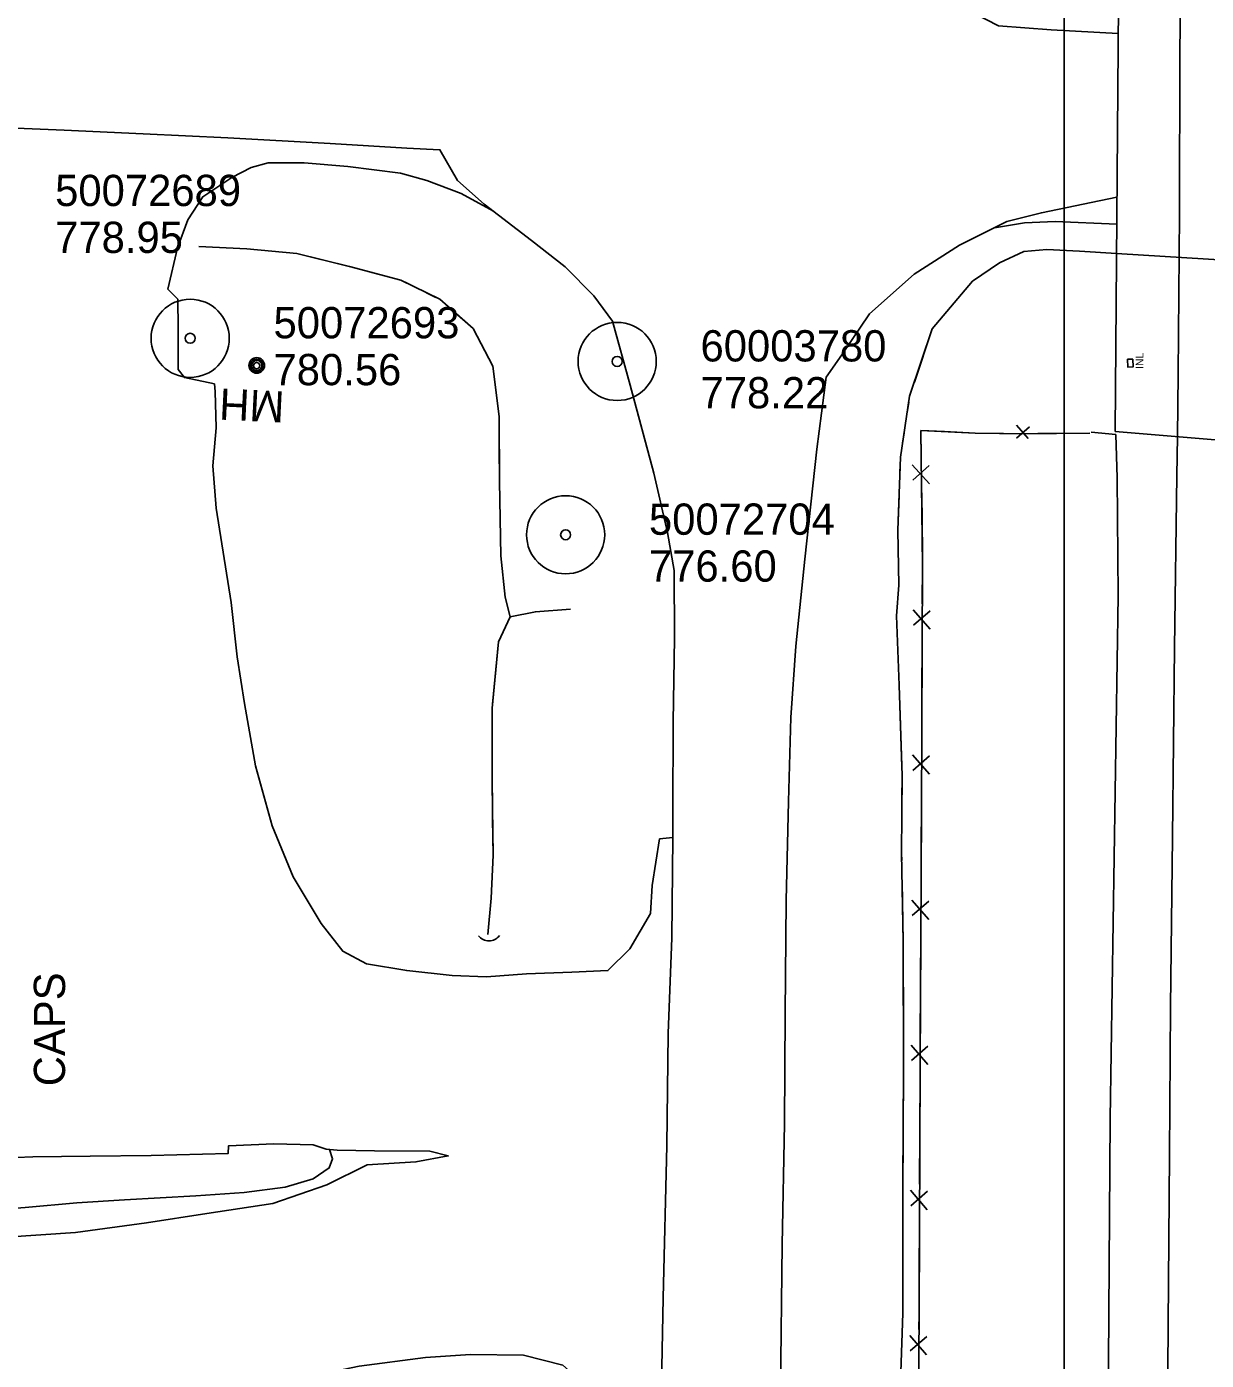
# Model space of a CAD drawing. Extents: x 591954 to 597000, y 198576 to 213500.
# Drawn here: x 593800.8 to 594027.3, y 204597.1 to 204853.1 of the extents above; entities that cross this region are included whole.
import ezdxf

# ---------------------------------------------------------------- set-up
doc = ezdxf.new("R2010")
doc.units = 0
for name, color, linetype in [('Level 10', 7, 'Continuous'), ('Level 11', 7, 'Continuous'), ('Level 15', 7, 'Continuous'), ('Level 16', 7, 'Continuous'), ('Level 17', 7, 'Continuous'), ('Level 19', 7, 'Continuous'), ('Level 6', 7, 'Continuous')]:
    doc.layers.add(name, color=color, linetype=linetype)

msp = doc.modelspace()

# ---------------------------------------------------------------- linework, layer by layer
at = {"layer": 'Level 10'}
for p, q in [((594000, 204500), (594000, 206500)), ((594000, 204500), (594000, 206500)), ((594000, 204500), (594000, 206000)), ((594000, 204000), (594000, 205500)), ((594000, 203500), (594000, 205000))]:
    msp.add_line(p, q, dxfattribs=at)
at = {"layer": 'Level 11'}
for points in [[(593950.48, 204940.73), (593951.05, 204934.39), (593952.29, 204922.71), (593954.97, 204909.56), (593958.15, 204894.43), (593961.95, 204883.36), (593965.83, 204875.09), (593970.65, 204867.79), (593974.61, 204862.06), (593980.17, 204856.96), (593987.4, 204853.29), (593997.5, 204852.51), (594010.4, 204851.83)], [(594022.76, 204897.49), (594022.54, 204875.93), (594022.24, 204847.98), (594022.19, 204817.13), (594021.94, 204786.42), (594021.78, 204774.42)], [(593791.02, 204833.98), (593808.02, 204833.27), (593823.21, 204832.55), (593839.44, 204831.79), (593859.12, 204830.68), (593873.81, 204829.8), (593880.16, 204829.49), (593883.57, 204823.57), (593888.64, 204819.05), (593897.72, 204812.1), (593904.21, 204807.02), (593909.73, 204801.46), (593913.31, 204796.6), (593916.69, 204784.31), (593921.23, 204767.39), (593923.86, 204756.03), (593925.16, 204748.73), (593925.23, 204735.76), (593924.93, 204719.68), (593924.89, 204702.24), (593924.86, 204697.49)], [(593890.44, 204817.68), (593884.23, 204821.08), (593877.62, 204823.56), (593872.62, 204824.98), (593862.5, 204826.29), (593854.12, 204826.99), (593847.18, 204827.01)], [(594010.16, 204820.36), (593995.67, 204817.39), (593989.04, 204815.71), (593979.91, 204811.2), (593971.2, 204805.58), (593962.63, 204797.96), (593957.32, 204790.14), (593954.3, 204785.86), (593952.52, 204771.98), (593950.25, 204750.88), (593948.49, 204734.2), (593947.55, 204720.51), (593947.08, 204704.38), (593946.66, 204685.38), (593946.43, 204663.69), (593946.32, 204642.47), (593945.89, 204619.32), (593945.56, 204591.42)], [(594010.11, 204815.21), (593998.32, 204815.74), (593992.41, 204815.46), (593986.64, 204814.52)], [(594021.78, 204774.42), (594021.68, 204766.91), (594021.23, 204733.87), (594020.85, 204697.5), (594020.43, 204664.97), (594020.23, 204636.55), (594020.02, 204603.94), (594019.79, 204577.76), (594019.36, 204543.85), (594018.8, 204510.12), (594018.68, 204480.65), (594018.25, 204441.53), (594018.05, 204410.9), (594017.91, 204399.22), (594017.15, 204332.99), (594016.82, 204297.15), (594016.34, 204268.02), (594016.06, 204236.2), (594015.78, 204207.45), (594015.48, 204178.53), (594015.23, 204165.45)], [(593924.86, 204697.49), (593924.7, 204678.23)], [(593924.7, 204678.23), (593923.99, 204659.86), (593923.72, 204638.26), (593923.06, 204609.1), (593922.53, 204582.42), (593922.49, 204571.57)]]:
    msp.add_lwpolyline(points, dxfattribs=at)
at = {"layer": 'Level 15'}
for p, q in [((593993.09, 204774.09), (593990.86, 204776.64)), ((593993.38, 204776.32), (593990.87, 204774.15)), ((593970.87, 204769.01), (593974.15, 204765.33)), ((593974.11, 204768.88), (593970.97, 204766.04)), ((593971.05, 204741.18), (593974.27, 204737.45)), ((593974.29, 204740.99), (593971.1, 204738.21)), ((593970.93, 204713.32), (593974.15, 204709.59)), ((593974.17, 204713.14), (593970.99, 204710.35)), ((593970.79, 204685.46), (593974.01, 204681.73)), ((593974.03, 204685.27), (593970.84, 204682.49)), ((593970.64, 204657.6), (593973.86, 204653.87)), ((593973.88, 204657.41), (593970.69, 204654.64)), ((593970.53, 204629.74), (593973.75, 204626.01)), ((593973.76, 204629.56), (593970.58, 204626.77)), ((593970.4, 204601.89), (593973.61, 204598.14)), ((593973.64, 204601.69), (593970.45, 204598.92))]:
    msp.add_line(p, q, dxfattribs=at)
for points in [[(594009.8, 204775.43), (594035.18, 204773.29), (594055.09, 204771.47), (594079.19, 204769.38), (594103.38, 204767.91), (594131.62, 204766.14), (594132.69, 204886.85), (594113.93, 204889.15), (594088.57, 204892.2), (594057.68, 204894.45), (594010.77, 204898.53), (594009.8, 204775.43)], [(594013.21, 204789.31), (594012.21, 204789.28), (594012.25, 204787.78), (594013.25, 204787.81), (594013.21, 204789.31)], [(594004.93, 204775.07), (593992.24, 204774.97), (593982.91, 204775.11), (593972.53, 204775.59), (593972.83, 204749.67), (593972.62, 204702.6), (593972.36, 204653.67), (593972.17, 204605.99), (593971.69, 204540.87), (593971.38, 204493.61), (593971.2, 204445.1), (593971, 204397.45), (593970.28, 204351.21), (593970.53, 204303.06), (593970.73, 204279)], [(593977.08, 204775.38), (593972.53, 204775.59), (593972.59, 204770.19)], [(593988.4, 204775.03), (593982.91, 204775.11), (593977.08, 204775.38)], [(594004.93, 204775.07), (593994.98, 204774.99)], [(594009.92, 204774.8), (594005.24, 204775.27)], [(594009.92, 204774.8), (594010.23, 204766.5), (594010.39, 204743.84), (594008.84, 204643.53), (594008.37, 204568.66), (594006.82, 204443.45), (594006.02, 204341.34)], [(593972.67, 204763.61), (593972.8, 204752.29)], [(593972.8, 204752.29), (593972.83, 204749.67), (593972.79, 204742.33)], [(593972.77, 204735.75), (593972.72, 204724.43)], [(593972.72, 204724.43), (593972.68, 204714.47)], [(593972.65, 204707.89), (593972.62, 204702.6), (593972.59, 204696.57)], [(593972.59, 204696.57), (593972.54, 204686.61)], [(593972.5, 204680.03), (593972.44, 204668.71)], [(593972.44, 204668.71), (593972.38, 204658.75)], [(593972.35, 204652.17), (593972.31, 204640.85)], [(593972.31, 204640.85), (593972.27, 204630.89)], [(593972.24, 204624.31), (593972.2, 204612.99)], [(593972.2, 204612.99), (593972.17, 204605.99), (593972.15, 204603.03)]]:
    msp.add_lwpolyline(points, dxfattribs=at)
msp.add_arc((593889.57, 204680.11), 2.5, 217.2794, 323.519, dxfattribs=at)
at = {"layer": 'Level 16'}
for centre, radius in [((593844.99, 204788.08), 1.5), ((593844.99, 204788.07), 1.22), ((593844.99, 204788.06), 0.968), ((593844.96, 204788.05), 0.605)]:
    msp.add_circle(centre, radius, dxfattribs=at)
at = {"layer": 'Level 17'}
for points in [[(593924.86, 204697.49), (593922.34, 204697.19), (593920.94, 204688.26), (593920.58, 204682.85), (593916.66, 204676.11), (593912.42, 204671.9), (593905.51, 204671.6), (593896.76, 204671.31), (593889.09, 204670.74), (593882.53, 204670.94), (593873.8, 204671.91), (593866.08, 204673.2), (593861.51, 204675.64), (593857.38, 204680.96), (593852.01, 204689.92), (593847.95, 204699.7), (593844.73, 204711.19), (593842.65, 204723.16), (593841.26, 204732.12), (593840.05, 204742.59), (593837.19, 204760.7), (593836.59, 204768.79), (593837.22, 204776.08), (593837.02, 204783.11), (593836.87, 204784.54), (593831.09, 204785.76), (593829.92, 204787.32), (593829.89, 204795.26), (593829.82, 204800.82), (593827.93, 204802.74), (593829.77, 204810.69), (593831.74, 204816.02), (593834.63, 204820.48), (593840.18, 204824.15), (593843.91, 204826.08), (593847.18, 204827.01)], [(593789.38, 204635.67), (593802.01, 204636.14), (593813.01, 204636.29), (593824.75, 204636.43), (593839.51, 204636.81), (593839.55, 204638.27), (593848.26, 204638.67), (593855.84, 204638.49), (593858.31, 204637.64), (593860.42, 204637.46), (593867.58, 204637.31), (593878.23, 204637.23), (593881.77, 204636.34), (593875.55, 204635.19), (593866.21, 204634.6), (593858.48, 204630.8), (593848.06, 204627.17), (593835.38, 204625.27), (593823.81, 204623.47), (593810.19, 204621.61), (593796.85, 204620.72)], [(593858.93, 204637.59), (593859.56, 204635.79), (593858.92, 204634.04), (593855.85, 204631.94), (593850.45, 204630.32), (593842.58, 204629.32), (593833.28, 204628.66), (593819.62, 204627.89), (593810.45, 204627.35), (593800.52, 204626.45), (593788.92, 204625.51), (593777.95, 204624.55), (593765.33, 204623.12), (593752.81, 204622.01), (593741.79, 204620.1), (593730.93, 204618.11), (593719.49, 204615.39), (593710.09, 204612.46), (593705.52, 204609.13), (593696.51, 204607.23), (593683.76, 204605.92), (593677.44, 204607.17)], [(593790.71, 204441.53), (593794.48, 204450.19), (593797.09, 204460.81), (593797.94, 204478.07), (593798.46, 204497.19), (593798.75, 204519.3), (593799.26, 204537.02), (593799.81, 204564.18), (593801.19, 204573.06), (593808.05, 204580.23), (593829.75, 204587.56), (593852.05, 204593.34), (593864.66, 204596), (593877.42, 204597.64), (593886.03, 204598.2), (593896.24, 204598.08), (593903.76, 204596.18), (593910.27, 204590.43), (593916.37, 204584.74), (593919.67, 204577.68), (593922.49, 204571.57)]]:
    msp.add_lwpolyline(points, dxfattribs=at)
at = {"layer": 'Level 19'}
for points in [[(593833.86, 204810.94), (593843.08, 204810.5), (593852.67, 204809.6), (593862.83, 204807.07), (593872.68, 204804.45), (593880.13, 204800.78), (593886.52, 204795.15), (593890.35, 204787.96), (593891.54, 204778.26), (593891.58, 204765.81), (593891.85, 204751.56), (593892.68, 204743.59), (593893.65, 204739.84)], [(593833.86, 204810.94), (593843.08, 204810.5), (593852.67, 204809.6), (593862.5, 204807.15)], [(593987.59, 204807.77), (593992.27, 204809.94), (593996.71, 204810.33), (594002.98, 204810.01), (594010.07, 204809.57)], [(594010.07, 204809.57), (594002.98, 204810.01), (593996.71, 204810.33), (593992.27, 204809.94), (593987.59, 204807.77)], [(594010.07, 204809.57), (594131.76, 204802.06)], [(593987.59, 204807.77), (593982.45, 204804.28), (593974.67, 204795.11), (593970.36, 204782.19), (593968.59, 204770.46), (593968.08, 204756.48), (593968.3, 204745.92), (593967.82, 204740)], [(593987.59, 204807.77), (593982.45, 204804.28), (593974.67, 204795.11), (593971.26, 204784.9)], [(593866.37, 204806.12), (593868.3, 204805.61)], [(593872.17, 204804.58), (593872.68, 204804.45), (593874, 204803.8)], [(593877.59, 204802.03), (593879.38, 204801.15)], [(593882.51, 204798.68), (593886.52, 204795.15), (593890.35, 204787.96), (593891.54, 204778.26), (593891.56, 204772.53)], [(593970.19, 204781.06), (593969.89, 204779.08)], [(593969.29, 204775.13), (593969, 204773.15)], [(593891.56, 204772.53), (593891.58, 204765.81), (593891.85, 204751.56), (593892.68, 204743.59), (593892.69, 204743.57)], [(593968.54, 204769.18), (593968.47, 204767.18)], [(593968.33, 204763.19), (593968.08, 204756.48), (593968.3, 204745.92), (593967.82, 204740)], [(593905.21, 204741.27), (593898.49, 204740.81), (593893.65, 204739.84), (593891.44, 204735), (593890.21, 204722.31), (593890.19, 204707.76), (593890.38, 204694.08), (593889.99, 204685.82), (593889.39, 204678.86)], [(593890.28, 204723.05), (593891.44, 204735), (593893.65, 204739.84), (593898.49, 204740.81), (593905.21, 204741.27)], [(593967.82, 204740), (593968.36, 204726.69), (593968.9, 204709.31), (593968.81, 204694.43), (593969.09, 204677.52), (593969.2, 204652.82), (593969.06, 204629.08), (593969.05, 204606.13), (593968.52, 204590.97)], [(593967.82, 204740), (593968.36, 204726.69), (593968.84, 204711.02)], [(593890.2, 204717.05), (593890.2, 204719.05)], [(593890.2, 204711.05), (593890.2, 204713.05)], [(593890.23, 204705.05), (593890.2, 204707.05)], [(593968.88, 204707.02), (593968.87, 204705.02)], [(593889.39, 204678.86), (593889.99, 204685.82), (593890.38, 204694.08), (593890.29, 204701.05)], [(593968.85, 204701.02), (593968.84, 204699.02)], [(593968.81, 204695.02), (593968.81, 204694.43), (593968.83, 204693.02)], [(593968.9, 204689.02), (593969.09, 204677.52), (593969.17, 204660.02)], [(593969.17, 204660.02), (593969.2, 204652.82), (593969.07, 204631.02)], [(593969.06, 204627.02), (593969.06, 204625.02)], [(593969.06, 204621.02), (593969.06, 204619.02)], [(593969.06, 204615.02), (593969.06, 204613.02)], [(593969.06, 204609.02), (593969.05, 204606.13), (593968.52, 204590.97), (593968.53, 204580.03)]]:
    msp.add_lwpolyline(points, dxfattribs=at)
at = {"layer": 'Level 6'}
for centre, radius in [((593832.21, 204793.29), 7.5), ((593832.21, 204793.29), 7.5), ((593832.21, 204793.29), 7.5), ((593832.21, 204793.29), 7.5), ((593832.21, 204793.29), 7.5), ((593832.21, 204793.29), 0.96), ((593832.21, 204793.29), 0.96), ((593832.21, 204793.29), 0.96), ((593832.21, 204793.29), 0.96), ((593832.21, 204793.29), 0.96), ((593914.2, 204788.85), 7.5), ((593914.2, 204788.85), 7.5), ((593914.2, 204788.85), 7.5), ((593914.2, 204788.85), 7.5), ((593914.2, 204788.85), 7.5), ((593914.2, 204788.85), 0.96), ((593914.2, 204788.85), 0.96), ((593914.2, 204788.85), 0.96), ((593914.2, 204788.85), 0.96), ((593914.2, 204788.85), 0.96), ((593904.3, 204755.58), 7.5), ((593904.3, 204755.58), 7.5), ((593904.3, 204755.58), 7.5), ((593904.3, 204755.58), 7.5), ((593904.3, 204755.58), 7.5), ((593904.3, 204755.58), 0.96), ((593904.3, 204755.58), 0.96), ((593904.3, 204755.58), 0.96), ((593904.3, 204755.58), 0.96), ((593904.3, 204755.58), 0.96)]:
    msp.add_circle(centre, radius, dxfattribs=at)

# ---------------------------------------------------------------- texts
at = {"layer": 'Level 15'}
msp.add_text('INL', height=1.5, rotation=90, dxfattribs=at).set_placement((594015.26, 204787.42))
at = {"layer": 'Level 16'}
for s, rotation, p in [('MH', 177.2518, (593850.44, 204783.09)), ('CAPS', 90, (593808.19, 204649.71))]:
    msp.add_text(s, height=6, rotation=rotation, dxfattribs=at).set_placement(p)
at = {"layer": 'Level 6'}
for s, p in [('50072689', (593806.28, 204818.68)), ('50072689', (593806.28, 204818.68)), ('50072689', (593806.28, 204818.68)), ('50072689', (593806.28, 204818.68)), ('50072689', (593806.28, 204818.68)), ('778.95', (593806.28, 204809.68)), ('778.95', (593806.28, 204809.68)), ('778.95', (593806.28, 204809.68)), ('778.95', (593806.28, 204809.68)), ('778.95', (593806.28, 204809.68)), ('50072693', (593848.21, 204793.29)), ('50072693', (593848.21, 204793.29)), ('50072693', (593848.21, 204793.29)), ('50072693', (593848.21, 204793.29)), ('50072693', (593848.21, 204793.29)), ('60003780', (593930.2, 204788.85)), ('60003780', (593930.2, 204788.85)), ('60003780', (593930.2, 204788.85)), ('60003780', (593930.2, 204788.85)), ('60003780', (593930.2, 204788.85)), ('780.56', (593848.21, 204784.29)), ('780.56', (593848.21, 204784.29)), ('780.56', (593848.21, 204784.29)), ('780.56', (593848.21, 204784.29)), ('780.56', (593848.21, 204784.29)), ('778.22', (593930.2, 204779.85)), ('778.22', (593930.2, 204779.85)), ('778.22', (593930.2, 204779.85)), ('778.22', (593930.2, 204779.85)), ('778.22', (593930.2, 204779.85)), ('50072704', (593920.3, 204755.58)), ('50072704', (593920.3, 204755.58)), ('50072704', (593920.3, 204755.58)), ('50072704', (593920.3, 204755.58)), ('50072704', (593920.3, 204755.58)), ('776.60', (593920.3, 204746.58)), ('776.60', (593920.3, 204746.58)), ('776.60', (593920.3, 204746.58)), ('776.60', (593920.3, 204746.58)), ('776.60', (593920.3, 204746.58))]:
    msp.add_text(s, height=6, dxfattribs=at).set_placement(p)

doc.saveas('drawing.dxf')
